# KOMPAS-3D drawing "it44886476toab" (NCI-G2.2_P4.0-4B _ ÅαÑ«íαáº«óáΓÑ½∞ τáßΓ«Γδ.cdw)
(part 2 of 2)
  Кривая без истории:10763
  Кривая без истории:10764
  Кривая без истории:10765
  Кривая без истории:10766
  Кривая без истории:10767
  Кривая без истории:10768
  Кривая без истории:10769
  Кривая без истории:10770
  Кривая без истории:10771
  Кривая без истории:10772
  Кривая без истории:10773
  Кривая без истории:10774
  Кривая без истории:10775
  Кривая без истории:10776
  Кривая без истории:10777
  Кривая без истории:10778
  Кривая без истории:10779
  Кривая без истории:10780
  Кривая без истории:10781
  Кривая без истории:10782
  Кривая без истории:10783
  Кривая без истории:10784
  Кривая без истории:10785
  Кривая без истории:10786
  Кривая без истории:10787
  Кривая без истории:10788
  Кривая без истории:10789
  Кривая без истории:10790
  Кривая без истории:10791
  Кривая без истории:10792
  Кривая без истории:10793
  Кривая без истории:10794
  Кривая без истории:10795
  Кривая без истории:10796
  Кривая без истории:10797
  Кривая без истории:10798
  Кривая без истории:10799
  Кривая без истории:10800
  Кривая без истории:10801
  Кривая без истории:10802
  Кривая без истории:10803
  Кривая без истории:10804
  Кривая без истории:10805
  Кривая без истории:10806
  Кривая без истории:10807
  Кривая без истории:10808
  Кривая без истории:10809
  Кривая без истории:10810
  Кривая без истории:10811
  Кривая без истории:10812
  Кривая без истории:10813
  Кривая без истории:10814
  Кривая без истории:10815
  Кривая без истории:10816
  Кривая без истории:10817
  Кривая без истории:10818
  Кривая без истории:10819
  Кривая без истории:10820
  Кривая без истории:10821
  Кривая без истории:10822
  Кривая без истории:10823
  Кривая без истории:10824
  Кривая без истории:10825
  Кривая без истории:10826
  Кривая без истории:10827
  Кривая без истории:10828
  Кривая без истории:10829
  Кривая без истории:10830
  Кривая без истории:10831
  Кривая без истории:10832
  Кривая без истории:10833
  Кривая без истории:10834
  Кривая без истории:10835
  Кривая без истории:10836
  Кривая без истории:10837
  Кривая без истории:10838
  Кривая без истории:10839
  Кривая без истории:10840
  Кривая без истории:10841
  Кривая без истории:10842
  Кривая без истории:10843
  Кривая без истории:10844
  Кривая без истории:10845
  Кривая без истории:10846
  Кривая без истории:10847
  Кривая без истории:10848
  Кривая без истории:10849
  Кривая без истории:10850
  Кривая без истории:10851
  Кривая без истории:10852
  Кривая без истории:10853
  Кривая без истории:10854
  Кривая без истории:10855
  Кривая без истории:10856
  Кривая без истории:10857
  Кривая без истории:10858
  Кривая без истории:10859
  Кривая без истории:10860
  Кривая без истории:10861
  Кривая без истории:10862
  Кривая без истории:10863
  Кривая без истории:10864
  Кривая без истории:10865
  Кривая без истории:10866
  Кривая без истории:10867
  Кривая без истории:10868
  Кривая без истории:10869
  Кривая без истории:10870
  Кривая без истории:10871
  Кривая без истории:10872
  Кривая без истории:10873
  Кривая без истории:10874
  Кривая без истории:10875
  Кривая без истории:10876
  Кривая без истории:10877
  Кривая без истории:10878
  Кривая без истории:10879
  Кривая без истории:10880
  Кривая без истории:10881
  Кривая без истории:10882
  Кривая без истории:10883
  Кривая без истории:10884
  Кривая без истории:10885
  Кривая без истории:10886
  Кривая без истории:10887
  Кривая без истории:10888
  Кривая без истории:10889
  Кривая без истории:10890
  Кривая без истории:10891
  Кривая без истории:10892
  Кривая без истории:10893
  Кривая без истории:10894
  Кривая без истории:10895
  Кривая без истории:10896
  Кривая без истории:10897
  Кривая без истории:10898
  Кривая без истории:10899
  Кривая без истории:10900
  Кривая без истории:10901
  Кривая без истории:10902
  Кривая без истории:10903
  Кривая без истории:10904
  Кривая без истории:10905
  Кривая без истории:10906
  Кривая без истории:10907
  Кривая без истории:10908
  Кривая без истории:10909
  Кривая без истории:10910
  Кривая без истории:10911
  Кривая без истории:10912
  Кривая без истории:10913
  Кривая без истории:10914
  Кривая без истории:10915
  Кривая без истории:10916
  Кривая без истории:10917
  Кривая без истории:10918
  Кривая без истории:10919
  Кривая без истории:10920
  Кривая без истории:10921
  Кривая без истории:10922
  Кривая без истории:10923
  Кривая без истории:10924
  Кривая без истории:10925
  Кривая без истории:10926
  Кривая без истории:10927
  Кривая без истории:10928
  Кривая без истории:10929
  Кривая без истории:10930
  Кривая без истории:10931
  Кривая без истории:10932
  Кривая без истории:10933
  Кривая без истории:10934
  Кривая без истории:10935
  Кривая без истории:10936
  Кривая без истории:10937
  Кривая без истории:10938
  Кривая без истории:10939
  Кривая без истории:10940
  Кривая без истории:10941
  Кривая без истории:10942
  Кривая без истории:10943
  Кривая без истории:10944
  Кривая без истории:10945
  Кривая без истории:10946
  Кривая без истории:10947
  Кривая без истории:10948
  Кривая без истории:10949
  Кривая без истории:10950
  Кривая без истории:10951
  Кривая без истории:10952
  Кривая без истории:10953
  Кривая без истории:10954
  Кривая без истории:10955
  Кривая без истории:10956
  Кривая без истории:10957
  Кривая без истории:10958
  Кривая без истории:10959
  Кривая без истории:10960
  Кривая без истории:10961
  Кривая без истории:10962
  Кривая без истории:10963
  Кривая без истории:10964
  Кривая без истории:10965
  Кривая без истории:10966
  Кривая без истории:10967
  Кривая без истории:10968
  Кривая без истории:10969
  Кривая без истории:10970
  Кривая без истории:10971
  Кривая без истории:10972
  Кривая без истории:10973
  Кривая без истории:10974
  Кривая без истории:10975
  Кривая без истории:10976
  Кривая без истории:10977
  Кривая без истории:10978
  Кривая без истории:10979
  Кривая без истории:10980
  Кривая без истории:10981
  Кривая без истории:10982
  Кривая без истории:10983
  Кривая без истории:10984
  Кривая без истории:10985
  Кривая без истории:10986
  Кривая без истории:10987
  Кривая без истории:10988
  Кривая без истории:10989
  Кривая без истории:10990
  Кривая без истории:10991
  Кривая без истории:10992
  Кривая без истории:10993
  Кривая без истории:10994
  Кривая без истории:10995
  Кривая без истории:10996
  Кривая без истории:10997
  Кривая без истории:10998
  Кривая без истории:10999
  Кривая без истории:11000
  Кривая без истории:11001
  Кривая без истории:11002
  Кривая без истории:11003
  Кривая без истории:11004
  Кривая без истории:11005
  Кривая без истории:11006
  Кривая без истории:11007
  Кривая без истории:11008
  Кривая без истории:11009
  Кривая без истории:11010
  Кривая без истории:11011
  Кривая без истории:11012
  Кривая без истории:11013
  Кривая без истории:11014
  Кривая без истории:11015
  Кривая без истории:11016
  Кривая без истории:11017
  Кривая без истории:11018
  Кривая без истории:11019
  Кривая без истории:11020
  Кривая без истории:11021
  Кривая без истории:11022
  Кривая без истории:11023
  Кривая без истории:11024
  Кривая без истории:11025
  Кривая без истории:11026
  Кривая без истории:11027
  Кривая без истории:11028
  Кривая без истории:11029
  Кривая без истории:11030
  Кривая без истории:11031
  Кривая без истории:11032
  Кривая без истории:11033
  Кривая без истории:11034
  Кривая без истории:11035
  Кривая без истории:11036
  Кривая без истории:11037
  Кривая без истории:11038
  Кривая без истории:11039
  Кривая без истории:11040
  Кривая без истории:11041
  Кривая без истории:11042
  Кривая без истории:11043
  Кривая без истории:11044
  Кривая без истории:11045
  Кривая без истории:11046
  Кривая без истории:11047
  Кривая без истории:11048
  Кривая без истории:11049
  Кривая без истории:11050
  Кривая без истории:11051
  Кривая без истории:11052
  Кривая без истории:11053
  Кривая без истории:11054
  Кривая без истории:11055
  Кривая без истории:11056
  Кривая без истории:11057
  Кривая без истории:11058
  Кривая без истории:11059
  Кривая без истории:11060
  Кривая без истории:11061
  Кривая без истории:11062
  Кривая без истории:11063
  Кривая без истории:11064
  Кривая без истории:11065
  Кривая без истории:11066
  Кривая без истории:11067
  Кривая без истории:11068
  Кривая без истории:11069
  Кривая без истории:11070
  Кривая без истории:11071
  Кривая без истории:11072
  Кривая без истории:11073
  Кривая без истории:11074
  Кривая без истории:11075
  Кривая без истории:11076
  Кривая без истории:11077
  Кривая без истории:11078
  Кривая без истории:11079
  Кривая без истории:11080
  Кривая без истории:11081
  Кривая без истории:11082
  Кривая без истории:11083
  Кривая без истории:11084
  Кривая без истории:11085
  Кривая без истории:11086
  Кривая без истории:11087
  Кривая без истории:11088
  Кривая без истории:11089
  Кривая без истории:11090
  Кривая без истории:11091
  Кривая без истории:11092
  Кривая без истории:11093
  Кривая без истории:11094
  Кривая без истории:11095
  Кривая без истории:11096
  Кривая без истории:11097
  Кривая без истории:11098
  Кривая без истории:11099
  Кривая без истории:11100
  Кривая без истории:11101
  Кривая без истории:11102
  Кривая без истории:11103
  Кривая без истории:11104
  Кривая без истории:11105
  Кривая без истории:11106
  Кривая без истории:11107
  Кривая без истории:11108
  Кривая без истории:11109
  Кривая без истории:11110
  Кривая без истории:11111
  Кривая без истории:11112
  Кривая без истории:11113
  Кривая без истории:11114
  Кривая без истории:11115
  Кривая без истории:11116
  Кривая без истории:11117
  Кривая без истории:11118
  Кривая без истории:11119
  Кривая без истории:11120
  Кривая без истории:11121
  Кривая без истории:11122
  Кривая без истории:11123
  Кривая без истории:11124
  Кривая без истории:11125
  Кривая без истории:11126
  Кривая без истории:11127
  Кривая без истории:11128
  Кривая без истории:11129
  Кривая без истории:11130
  Кривая без истории:11131
  Кривая без истории:11132
  Кривая без истории:11133
  Кривая без истории:11134
  Кривая без истории:11135
  Кривая без истории:11136
  Кривая без истории:11137
  Кривая без истории:11138
  Кривая без истории:11139
  Кривая без истории:11140
  Кривая без истории:11141
  Кривая без истории:11142
  Кривая без истории:11143
  Кривая без истории:11144
  Кривая без истории:11145
  Кривая без истории:11146
  Кривая без истории:11147
  Кривая без истории:11148
  Кривая без истории:11149
  Кривая без истории:11150
  Кривая без истории:11151
  Кривая без истории:11152
  Кривая без истории:11153
  Кривая без истории:11154
  Кривая без истории:11155
  Кривая без истории:11156
  Кривая без истории:11157
  Кривая без истории:11158
  Кривая без истории:11159
  Кривая без истории:11160
  Кривая без истории:11161
  Кривая без истории:11162
  Кривая без истории:11163
  Кривая без истории:11164
  Кривая без истории:11165
  Кривая без истории:11166
  Кривая без истории:11167
  Кривая без истории:11168
  Кривая без истории:11169
  Кривая без истории:11170
  Кривая без истории:11171
  Кривая без истории:11172
  Кривая без истории:11173
  Кривая без истории:11174
  Кривая без истории:11175
  Кривая без истории:11176
  Кривая без истории:11177
  Кривая без истории:11178
  Кривая без истории:11179
  Кривая без истории:11180
  Кривая без истории:11181
  Кривая без истории:11182
  Кривая без истории:11183
  Кривая без истории:11184
  Кривая без истории:11185
  Кривая без истории:11186
  Кривая без истории:11187
  Кривая без истории:11188
  Кривая без истории:11189
  Кривая без истории:11190
  Кривая без истории:11191
  Кривая без истории:11192
  Кривая без истории:11193
  Кривая без истории:11194
  Кривая без истории:11195
  Кривая без истории:11196
  Кривая без истории:11197
  Кривая без истории:11198
  Кривая без истории:11199
  Кривая без истории:11200
  Кривая без истории:11201
  Кривая без истории:11202
  Кривая без истории:11203
  Кривая без истории:11204
  Кривая без истории:11205
  Кривая без истории:11206
  Кривая без истории:11207
  Кривая без истории:11208
  Кривая без истории:11209
  Кривая без истории:11210
  Кривая без истории:11211
  Кривая без истории:11212
  Кривая без истории:11213
  Кривая без истории:11214
  Кривая без истории:11215
  Кривая без истории:11216
  Кривая без истории:11217
  Кривая без истории:11218
  Кривая без истории:11219
  Кривая без истории:11220
  Кривая без истории:11221
  Кривая без истории:11222
  Кривая без истории:11223
  Кривая без истории:11224
  Кривая без истории:11225
  Кривая без истории:11226
  Кривая без истории:11227
  Кривая без истории:11228
  Кривая без истории:11229
  Кривая без истории:11230
  Кривая без истории:11231
  Кривая без истории:11232
  Кривая без истории:11233
  Кривая без истории:11234
  Кривая без истории:11235
  Кривая без истории:11236
  Кривая без истории:11237
  Кривая без истории:11238
  Кривая без истории:11239
  Кривая без истории:11240
  Кривая без истории:11241
  Кривая без истории:11242
  Кривая без истории:11243
  Кривая без истории:11244
  Кривая без истории:11245
  Кривая без истории:11246
  Кривая без истории:11247
  Кривая без истории:11248
  Кривая без истории:11249
  Кривая без истории:11250
  Кривая без истории:11251
  Кривая без истории:11252
  Кривая без истории:11253
  Кривая без истории:11254
  Кривая без истории:11255
  Кривая без истории:11256
  Кривая без истории:11257
  Кривая без истории:11258
  Кривая без истории:11259
  Кривая без истории:11260
  Кривая без истории:11261
  Кривая без истории:11262
  Кривая без истории:11263
  Кривая без истории:11264
  Кривая без истории:11265
  Кривая без истории:11266
  Кривая без истории:11267
  Кривая без истории:11268
  Кривая без истории:11269
  Кривая без истории:11270
  Кривая без истории:11271
  Кривая без истории:11272
  Кривая без истории:11273
  Кривая без истории:11274
  Кривая без истории:11275
  Кривая без истории:11276
  Кривая без истории:11277
  Кривая без истории:11278
  Кривая без истории:11279
  Кривая без истории:11280
  Кривая без истории:11281
  Кривая без истории:11282
  Кривая без истории:11283
  Кривая без истории:11284
  Кривая без истории:11285
  Кривая без истории:11286
  Кривая без истории:11287
  Кривая без истории:11288
  Кривая без истории:11289
  Кривая без истории:11290
  Кривая без истории:11291
  Кривая без истории:11292
  Кривая без истории:11293
  Кривая без истории:11294
  Кривая без истории:11295
  Кривая без истории:11296
  Кривая без истории:11297
  Кривая без истории:11298
  Кривая без истории:11299
  Кривая без истории:11300
  Кривая без истории:11301
  Кривая без истории:11302
  Кривая без истории:11303
  Кривая без истории:11304
  Кривая без истории:11305
  Кривая без истории:11306
  Кривая без истории:11307
  Кривая без истории:11308
  Кривая без истории:11309
  Кривая без истории:11310
  Кривая без истории:11311
  Кривая без истории:11312
  Кривая без истории:11313
  Кривая без истории:11314
  Кривая без истории:11315
  Кривая без истории:11316
  Кривая без истории:11317
  Кривая без истории:11318
  Кривая без истории:11319
  Кривая без истории:11320
  Кривая без истории:11321
  Кривая без истории:11322
  Кривая без истории:11323
  Кривая без истории:11324
  Кривая без истории:11325
  Кривая без истории:11326
  Кривая без истории:11327
  Кривая без истории:11328
  Кривая без истории:11329
  Кривая без истории:11330
  Кривая без истории:11331
  Кривая без истории:11332
  Кривая без истории:11333
  Кривая без истории:11334
  Кривая без истории:11335
  Кривая без истории:11336
  Кривая без истории:11337
  Кривая без истории:11338
  Кривая без истории:11339
  Кривая без истории:11340
  Кривая без истории:11341
  Кривая без истории:11342
  Кривая без истории:11343
  Кривая без истории:11344
  Кривая без истории:11345
  Кривая без истории:11346
  Кривая без истории:11347
  Кривая без истории:11348
  Кривая без истории:11349
  Кривая без истории:11350
  Кривая без истории:11351
  Кривая без истории:11352
  Кривая без истории:11353
  Кривая без истории:11354
  Кривая без истории:11355
  Кривая без истории:11356
  Кривая без истории:11357
  Кривая без истории:11358
  Кривая без истории:11359
  Кривая без истории:11360
  Кривая без истории:11361
  Кривая без истории:11362
  Кривая без истории:11363
  Кривая без истории:11364
  Кривая без истории:11365
  Кривая без истории:11366
  Кривая без истории:11367
  Кривая без истории:11368
  Кривая без истории:11369
  Кривая без истории:11370
  Кривая без истории:11371
  Кривая без истории:11372
  Кривая без истории:11373
  Кривая без истории:11374
  Кривая без истории:11375
  Кривая без истории:11376
  Кривая без истории:11377
  Кривая без истории:11378
  Кривая без истории:11379
  Кривая без истории:11380
  Кривая без истории:11381
  Кривая без истории:11382
  Кривая без истории:11383
  Кривая без истории:11384
  Кривая без истории:11385
  Кривая без истории:11386
  Кривая без истории:11387
  Кривая без истории:11388
  Кривая без истории:11389
  Кривая без истории:11390
  Кривая без истории:11391
  Кривая без истории:11392
  Кривая без истории:11393
  Кривая без истории:11394
  Кривая без истории:11395
  Кривая без истории:11396
  Кривая без истории:11397
  Кривая без истории:11398
  Кривая без истории:11399
  Кривая без истории:11400
  Кривая без истории:11401
  Кривая без истории:11402
  Кривая без истории:11403
  Кривая без истории:11404
  Кривая без истории:11405
  Кривая без истории:11406
  Кривая без истории:11407
  Кривая без истории:11408
  Кривая без истории:11409
  Кривая без истории:11410
  Кривая без истории:11411
  Кривая без истории:11412
  Кривая без истории:11413
  Кривая без истории:11414
  Кривая без истории:11415
  Кривая без истории:11416
  Кривая без истории:11417
  Кривая без истории:11418
  Кривая без истории:11419
  Кривая без истории:11420
  Кривая без истории:11421
  Кривая без истории:11422
  Кривая без истории:11423
  Кривая без истории:11424
  Кривая без истории:11425
  Кривая без истории:11426
  Кривая без истории:11427
  Кривая без истории:11428
  Кривая без истории:11429
  Кривая без истории:11430
  Кривая без истории:11431
  Кривая без истории:11432
  Кривая без истории:11433
  Кривая без истории:11434
  Кривая без истории:11435
  Кривая без истории:11436
  Кривая без истории:11437
  Кривая без истории:11438
  Кривая без истории:11439
  Кривая без истории:11440
  Кривая без истории:11441
  Кривая без истории:11442
  Кривая без истории:11443
  Кривая без истории:11444
  Кривая без истории:11445
  Кривая без истории:11446
  Кривая без истории:11447
  Кривая без истории:11448
  Кривая без истории:11449
  Кривая без истории:11450
  Кривая без истории:11451
  Кривая без истории:11452
  Кривая без истории:11453
  Кривая без истории:11454
  Кривая без истории:11455
  Кривая без истории:11456
  Кривая без истории:11457
  Кривая без истории:11458
  Кривая без истории:11459
  Кривая без истории:11460
  Кривая без истории:11461
  Кривая без истории:11462
  Кривая без истории:11463
  Кривая без истории:11464
  Кривая без истории:11465
  Кривая без истории:11466
  Кривая без истории:11467
  Кривая без истории:11468
  Кривая без истории:11469
  Кривая без истории:11470
  Кривая без истории:11471
  Кривая без истории:11472
  Кривая без истории:11473
  Кривая без истории:11474
  Кривая без истории:11475
  Кривая без истории:11476
  Кривая без истории:11477
  Кривая без истории:11478
  Кривая без истории:11479
  Кривая без истории:11480
  Кривая без истории:11481
  Кривая без истории:11482
  Кривая без истории:11483
  Кривая без истории:11484
  Кривая без истории:11485
  Кривая без истории:11486
  Кривая без истории:11487
  Кривая без истории:11488
  Кривая без истории:11489
  Кривая без истории:11490
  Кривая без истории:11491
  Кривая без истории:11492
  Кривая без истории:11493
  Кривая без истории:11494
  Кривая без истории:11495
  Кривая без истории:11496
  Кривая без истории:11497
  Кривая без истории:11498
  Кривая без истории:11499
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Dimensions and other numbers on the sheet: 4±1; 1:1; 1; 13.01.25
